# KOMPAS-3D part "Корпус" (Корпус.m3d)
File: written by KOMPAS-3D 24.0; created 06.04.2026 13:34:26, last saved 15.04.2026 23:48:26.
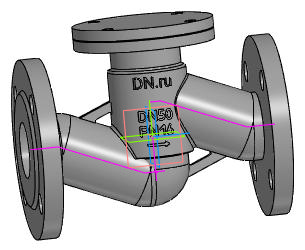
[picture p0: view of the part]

Document properties: Автор: R2D2; Полное имя файла: E:\Работа\Зайцев\VSO3131M-F-S Клапан запорный DN.ru Ду15-100 Ру16\DN50\исходные материалы\Корпус.m3d

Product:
- Body: Труба / Нестандартная труба / L = 116.1 мм  | qty 1
    Материал: Нестандартная труба (density 7856 kg/m3)
    Масса: 13.252607
    Раздел спецификации: Детали
    Примечание: 2,58 кг
    additional columns: Pipeline; 0.06; 0; 0; 0.002; 0.11611; true; 0.04
- Body: Труба / Нестандартная труба / L = 145.1 мм  | qty 1
    Материал: Нестандартная труба (density 7856 kg/m3)
    Масса: 13.252607
    Раздел спецификации: Детали
    Примечание: 3,22 кг
    additional columns: Pipeline; 0.06; 0; 0; 0.002; 0.14505; true; 0.04
- Body: Тело 4  | qty 1
    Материал: Нестандартная труба (density 7856 kg/m3)
    Масса: 13.252607
- Body: Тело 5  | qty 1
    Материал: Нестандартная труба (density 7856 kg/m3)
    Масса: 13.252607
- Body: Тело 8  | qty 1
    Материал: Нестандартная труба (density 7856 kg/m3)
    Масса: 13.252607
- Body: Тело 9  | qty 1
    Материал: Нестандартная труба (density 7856 kg/m3)
    Масса: 13.252607
- Part/product: Корпус
    Масса: 6.9

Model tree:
1. Труба
2. Труба:1  (labels: {F703FF30-5BE6-4673-A7F1-8EDA1BE1E2D1}; SHAPEOBJECT3D_ATTR_BUTT; SHAPEOBJECT3D_ATTR_VALID; SHAPEOBJECT3D_ATTR_BUTT_AREA)
     PIPE_R = 7
3. Труба:2  (labels: {F703FF30-5BE6-4673-A7F1-8EDA1BE1E2D1}; SHAPEOBJECT3D_ATTR_BUTT; SHAPEOBJECT3D_ATTR_VALID; SHAPEOBJECT3D_ATTR_BUTT_AREA)
     PIPE_R = 5
4. Колонна
5. Элемент выдавливания:1
     Смещение 1 = -1; Смещение 2 = -5
6. Скругление:17  (with: Ребро.Элемент выдавливания:1)
     Радиус = 1
7. Скругление:18  (with: Ребро.Элемент выдавливания:1)
8. Скругление:24  (with: Ребро.Элемент выдавливания:1)
     Радиус = 0.5
9. Элемент выдавливания:2
     Расстояние 1 = 6
10. Скругление:19  (with: Ребро.Элемент выдавливания:2)
     Радиус = 2
11. Эскиз:4  (with: Грань.Элемент выдавливания:1)
12. Элемент выдавливания:3
     Расстояние 1 = 27.5
13. Скругление:21  (with: Ребро.Элемент выдавливания:3)
14. ОТЛИВКА
15. Скругление:6  (with: Грань.Элемент выдавливания:1)
     Радиус = 2
16. Элемент выдавливания:6  (with: Грань.Элемент выдавливания:1)
     Смещение 1 = 4
17. ЛЕЙБЛ
18. Элемент выдавливания:7  (with: Грань.Элемент выдавливания:1)
     Расстояние 1 = 35.9996; Смещение 1 = 1
19. Фланец верх  (with: Ребро.Операция без истории:1)  (labels: Клапан запорный DN.ru Ду50 Ру16)
20. Элемент вращения:2
     Угол 1 = 360
21. Эскиз:12  (with: Грань.Элемент вращения:2)
22. Элемент выдавливания:9  (with: Грань.Элемент вращения:2)
     Расстояние 2 = 20
23. Массив по концентрической сетке:1  (with: Элемент выдавливания:9, Эскиз:12, Грань.Элемент вращения:2)  (4 pattern instances)
     Шаг 2 = 360
24. Фланец
25. Элемент вращения:1
     Угол 1 = 360
26. отвертие во фланце  (with: Грань.Элемент вращения:1)
27. Элемент выдавливания:8
28. Массив по концентрической сетке:2  (with: Элемент выдавливания:8, Эскиз:10, Грань.Элемент вращения:1)  (4 pattern instances)
     Шаг 2 = 360
29. Зеркальный массив:1
30. Экземпляр ( 1 )
31. Экземпляр ( 2 )  (with: Элемент вращения:1, Массив по концентрической сетке:2, Экземпляр ( 1 ), Элемент выдавливания:8)
32. Экземпляр ( 3 )  (with: Элемент выдавливания:8)
33. Экземпляр ( 4 )  (with: Элемент выдавливания:8)
34. Скругление:25  (with: Ребро.Элемент вращения:2)
     Радиус = 2
35. Скругление:26
     Радиус = 2

Expressions: DS/2+3; D1/2; DN/2; DS-v977*4; LL/2; D1-v1234*2; D/2+10
Referenced files in C:\Program Files\ASCON\KOMPAS-3D v24\Libs\Pipeline\: StylesTemplate.a3d, TemplateHPH, InsulationStylesTemplate.a3d, Insulation
Referenced files in C:\Program Files\ASCON\KOMPAS-3D v24\Templates\: Констр. чертеж А3 гориз. перв. лист.cdt
Referenced files in E:\Работа\Зайцев\VSO3131M-F-S Клапан запорный DN.ru Ду15-100 Ру40\DN20\исходные материалы\: 
Referenced files in E:\Работа\Зайцев\VSO3131M-F-S Клапан запорный DN.ru Ду15-100 Ру16\DN50\исходные материалы\: VSO3131M-F-S Клапан запорный DN.ru Ду50 Ру16.a3d
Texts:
  Отводы ГОСТ 17375-2001
  Констр. чертеж А3 гориз. перв. лист.cdt
  GOST 26.020 Pr3
  var3D
  смещение колонны вниз
  LL-10
  DN+10
  Труба / Нестандартная труба / L = %s мм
